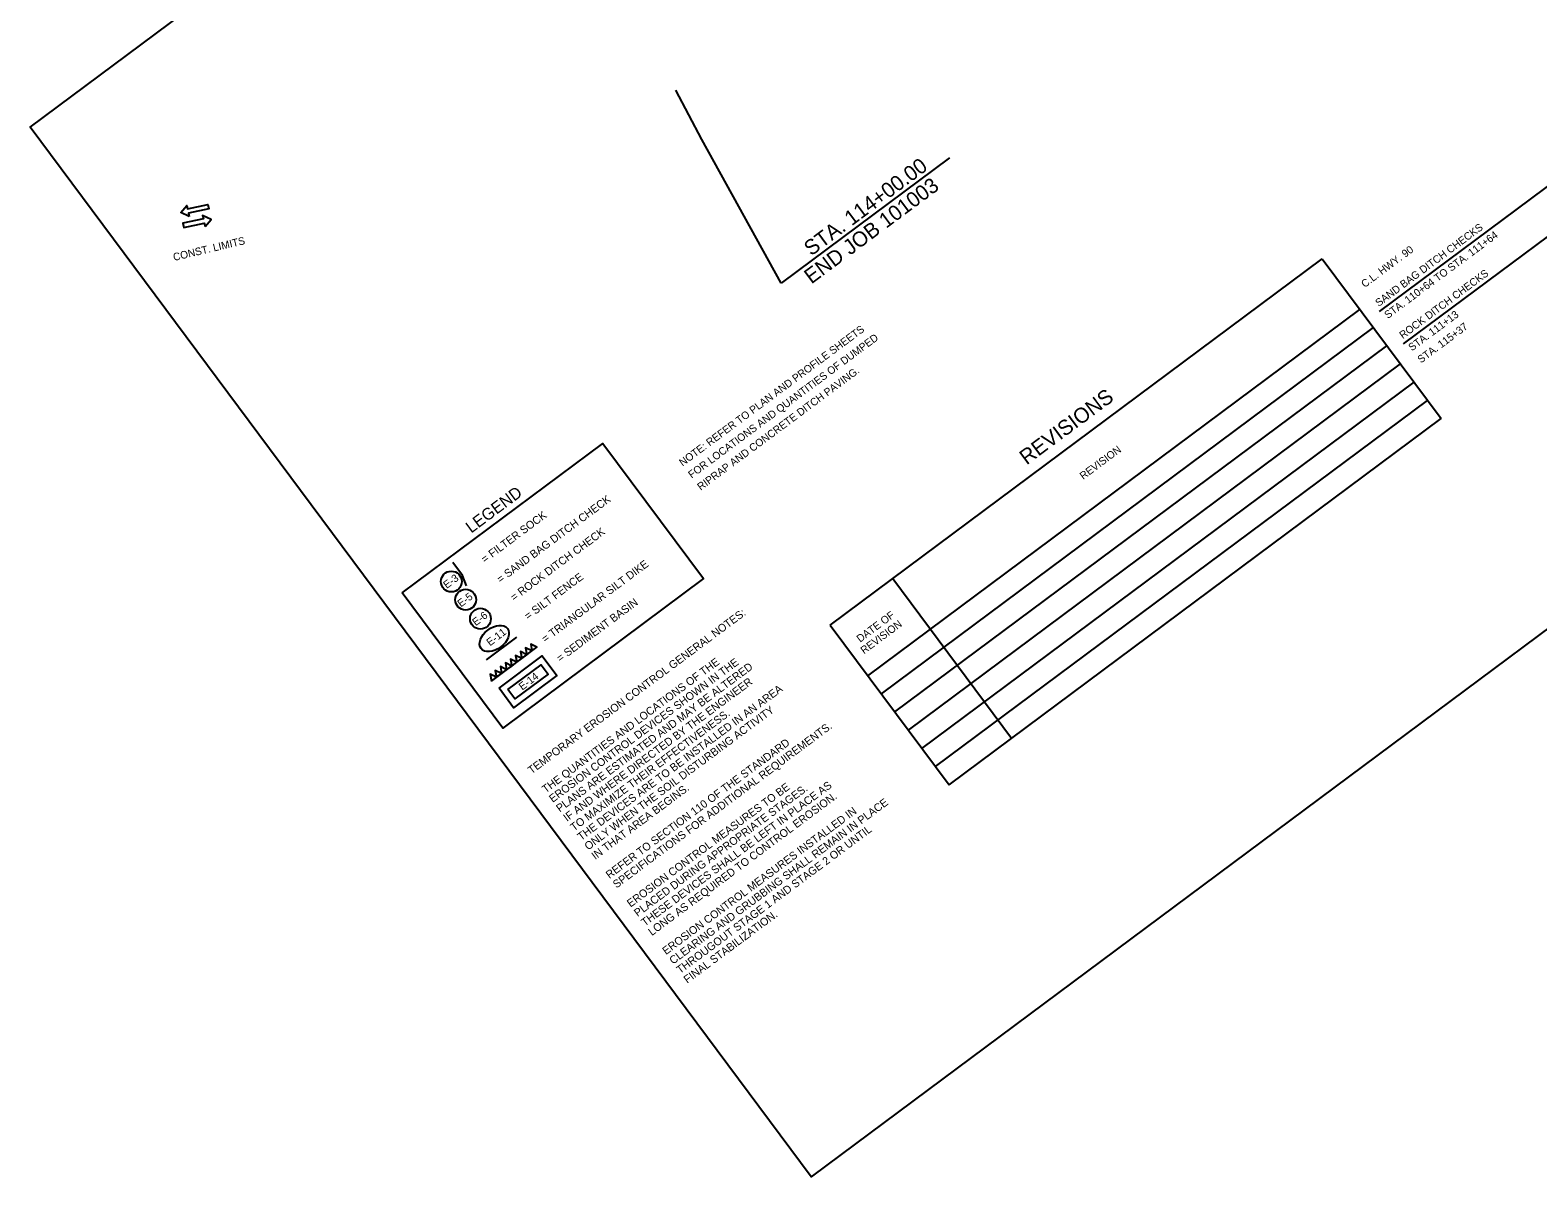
# Model space of a CAD drawing. Extents: x 1571137 to 1573037, y 731597 to 733459.
# Drawn here: x 1571137 to 1572334, y 731597 to 732507 of the extents above; entities that cross this region are included whole.
import ezdxf

# ---------------------------------------------------------------- set-up
doc = ezdxf.new("R2010")
doc.units = 0
for name, color, linetype in [('Default', 7, 'Continuous'), ('R_Annotation', 7, 'Continuous'), ('R_Contour Annot', 7, 'Continuous'), ('R_Erosion', 7, 'Continuous'), ('R_MOT', 7, 'Continuous'), ('S_BASELINE', 7, 'Continuous'), ('S_MSC_PT_SYM', 7, 'Continuous')]:
    doc.layers.add(name, color=color, linetype=linetype)

msp = doc.modelspace()

# ---------------------------------------------------------------- linework, layer by layer
at = {"layer": 'Default'}
msp.add_lwpolyline([(1571499.2, 732007.6), (1571523.4, 732025.6)], dxfattribs=at)
at = {"layer": 'R_Annotation'}
for p, q in [((1572208, 732284), (1572449.8, 732463.9)), ((1572227.1, 732258.3), (1572468.7, 732438.1)), ((1571866.8, 732405.9), (1571733.2, 732306.5))]:
    msp.add_line(p, q, dxfattribs=at)
msp.add_lwpolyline([(1571733.2, 732306.5), (1571670.2, 732420.6), (1571649.5, 732459.7)], dxfattribs=at)
msp.add_lwpolyline([(1571432.2, 732060.7), (1571591.6, 732179.3), (1571671.4, 732072), (1571512.1, 731953.4)], close=True, dxfattribs=at)
at = {"layer": 'R_Erosion'}
msp.add_line((1571503.2, 731990.7), (1571539.3, 732017.6), dxfattribs=at)
for points in [[(1571483.4, 732066.2), (1571480.1, 732074.6), (1571472.5, 732084.7)], [(1571503.2, 731990.7), (1571539.3, 732017.6)]]:
    msp.add_lwpolyline(points, dxfattribs=at)
for points in [[(1571509.2, 731985.2), (1571543.5, 732010.7), (1571555.1, 731995.2), (1571520.7, 731969.6)], [(1571523.3, 732005.6), (1571527.3, 732008.6), (1571522.3, 732011.1)], [(1571527.3, 732008.6), (1571531.3, 732011.6), (1571526.3, 732014.1)], [(1571531.3, 732011.6), (1571535.3, 732014.6), (1571530.3, 732017.1)], [(1571535.3, 732014.6), (1571539.3, 732017.6), (1571534.3, 732020.1)], [(1571507.2, 731993.7), (1571511.2, 731996.7), (1571506.2, 731999.2)], [(1571511.2, 731996.7), (1571515.2, 731999.7), (1571510.3, 732002.2)], [(1571515.2, 731999.7), (1571519.3, 732002.6), (1571514.3, 732005.2)], [(1571516.2, 731984.1), (1571542.5, 732003.7), (1571548.1, 731996.2), (1571521.8, 731976.6)], [(1571519.3, 732002.6), (1571523.3, 732005.6), (1571518.3, 732008.1)], [(1571503.2, 731990.7), (1571507.2, 731993.7), (1571502.2, 731996.2)]]:
    msp.add_lwpolyline(points, close=True, dxfattribs=at)
for centre in [(1571471.3, 732069.7), (1571482.7, 732055.3), (1571494.4, 732040.2)]:
    msp.add_circle(centre, 8.26, dxfattribs=at)
msp.add_ellipse((1571505.4, 732024.5), major_axis=(10.5, 8), ratio=0.638788, dxfattribs=at)
at = {"layer": 'R_MOT'}
for points in [[(1571263.1, 732359.4), (1571256.5, 732362.6), (1571261.3, 732368.2), (1571261.8, 732365.4), (1571278, 732368.9), (1571278.7, 732365.6), (1571262.6, 732362.1)], [(1571275.8, 732351.4), (1571280.6, 732357.1), (1571273.9, 732360.2), (1571274.5, 732357.5), (1571258.3, 732354), (1571259, 732350.7), (1571275.2, 732354.2)]]:
    msp.add_lwpolyline(points, close=True, dxfattribs=at)
at = {"layer": 'S_BASELINE'}
for p, q in [((1571772.1, 732035.1), (1572162.6, 732325.8)), ((1572162.6, 732325.8), (1572256.9, 732199)), ((1571801.9, 731995), (1572192.5, 732285.7)), ((1571812.7, 731980.6), (1572203.2, 732271.2)), ((1571823.4, 731966.2), (1572214, 732256.8)), ((1571834.2, 731951.7), (1572224.7, 732242.4)), ((1571844.9, 731937.3), (1572235.5, 732227.9)), ((1571855.7, 731922.8), (1572246.2, 732213.5)), ((1571866.4, 731908.4), (1572256.9, 732199)), ((1571821.7, 732072), (1571916, 731945.3)), ((1571772.1, 732035.1), (1571866.4, 731908.4))]:
    msp.add_line(p, q, dxfattribs=at)
at = {"layer": 'S_MSC_PT_SYM'}
msp.add_lwpolyline([(1572536.7, 733221.6), (1573036.7, 732549.8), (1571756.9, 731597.3), (1571137, 732430.2), (1572086.8, 733137.2), (1572116.3, 733097.5), (1572258.8, 733203.6), (1572269.5, 733189.2), (1572284.1, 733200.1), (1572282.1, 733202.7), (1572344.4, 733249.1)], dxfattribs=at)

# ---------------------------------------------------------------- texts
at = {"layer": 'Default'}
for s, height, p in [('LEGEND', 9.37, (1571487.1, 732107.7)), ('= SAND BAG DITCH CHECK', 6.25, (1571510.3, 732068.2)), ('= FILTER SOCK', 6.25, (1571497.9, 732084.1)), ('= ROCK DITCH CHECK', 6.25, (1571521.1, 732053.8)), ('= TRIANGULAR SILT DIKE', 6.25, (1571545.9, 732020.9)), ('= SILT FENCE', 6.25, (1571532.2, 732039)), ('= SEDIMENT BASIN', 6.25, (1571557.7, 732005.5))]:
    msp.add_text(s, height=height, rotation=36.6576, dxfattribs=at).set_placement(p)
at = {"layer": 'R_Annotation'}
for s, height, rotation, p in [('STA. 114+00.00', 12, 36.6576, (1571756.9, 732327.6)), ('END JOB 101003', 12, 36.6576, (1571757.1, 732305.4)), ('SAND BAG DITCH CHECKS', 6, 36.6576, (1572207.5, 732287.6)), ('STA. 110+64 TO STA. 111+64', 6, 36.6576, (1572214.7, 732278)), ('CONST. LIMITS', 6, 13.3424, (1571251.2, 732324.1)), ('C.L. HWY. 90', 6, 36.6576, (1572196.3, 732302.6)), ('ROCK DITCH CHECKS', 6, 36.6576, (1572226.6, 732262)), ('STA. 111+13', 6, 36.6576, (1572233.8, 732252.3)), ('NOTE: REFER TO PLAN AND PROFILE SHEETS', 6, 36.6576, (1571654.9, 732160.9)), ('STA. 115+37', 6, 36.6576, (1572241, 732242.7)), ('FOR LOCATIONS AND QUANTITIES OF DUMPED', 6, 36.6576, (1571662.1, 732151.3)), ('RIPRAP AND CONCRETE DITCH PAVING.', 6, 36.6576, (1571669.3, 732141.7))]:
    msp.add_text(s, height=height, rotation=rotation, dxfattribs=at).set_placement(p)
at = {"layer": 'R_Contour Annot'}
for s, p in [('TEMPORARY EROSION CONTROL GENERAL NOTES:', (1571535, 731916.6)), ('THE QUANTITIES AND LOCATIONS OF THE', (1571546.2, 731901.5)), ('EROSION CONTROL DEVICES SHOWN IN THE ', (1571551.8, 731894)), ('PLANS ARE ESTIMATED AND MAY BE ALTERED ', (1571557.4, 731886.4)), ('IF AND WHERE DIRECTED BY THE ENGINEER ', (1571563.1, 731878.9)), ('THE DEVICES ARE TO BE INSTALLED IN AN AREA ', (1571574.3, 731863.8)), ('TO MAXIMIZE THEIR EFFECTIVENESS. ', (1571568.7, 731871.3)), ('ONLY WHEN THE SOIL DISTURBING ACTIVITY', (1571579.9, 731856.2)), ('SPECIFICATIONS FOR ADDITIONAL REQUIREMENTS.', (1571602.4, 731826)), ('REFER TO SECTION 110 OF THE STANDARD ', (1571596.8, 731833.6)), ('IN THAT AREA BEGINS.', (1571585.5, 731848.7)), ('EROSION CONTROL MEASURES TO BE', (1571613.6, 731810.9)), ('PLACED DURING APPROPRIATE STAGES. ', (1571619.2, 731803.4)), ('THESE DEVICES SHALL BE LEFT IN PLACE AS ', (1571624.9, 731795.8)), ('LONG AS REQUIRED TO CONTROL EROSION.', (1571630.5, 731788.3)), ('EROSION CONTROL MEASURES INSTALLED IN', (1571641.7, 731773.2)), ('CLEARING AND GRUBBING SHALL REMAIN IN PLACE', (1571647.3, 731765.6)), ('THROUGOUT STAGE 1 AND STAGE 2 OR UNTIL', (1571652.9, 731758.1)), ('FINAL STABILIZATION.', (1571658.6, 731750.5))]:
    msp.add_text(s, height=6.25, rotation=36.6576, dxfattribs=at).set_placement(p)
at = {"layer": 'R_Erosion'}
for s, rotation, p in [('E-3', 36.6576, (1571467.7, 732063.8)), ('E-5 ', 36.6576, (1571478.9, 732049.1)), ('E-6 ', 36.6576, (1571490.7, 732034.2)), ('E-11', 37.2648, (1571502, 732018.2)), ('E-14', 36.6576, (1571527.6, 731983.1))]:
    msp.add_text(s, height=6, rotation=rotation, dxfattribs=at).set_placement(p)
at = {"layer": 'S_BASELINE'}
for s, height, p in [('REVISIONS', 12, (1571928, 732161.8)), ('REVISION', 6, (1571972.9, 732150.3)), ('DATE OF', 6, (1571795.8, 732021.1)), ('REVISION', 6, (1571798.9, 732011.9))]:
    msp.add_text(s, height=height, rotation=36.6576, dxfattribs=at).set_placement(p)

doc.saveas('drawing.dxf')
